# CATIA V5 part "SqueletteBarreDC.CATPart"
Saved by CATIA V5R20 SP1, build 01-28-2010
Part number: SqueletteBarreDC
Publications: "Point.1", "Point.2", "Droite.1", "Droite.2", "Droite.3", "Point.3", "Droite.4", "LongueurDC"
Bounding box of the stored display mesh (mm): x -20 to 20, y -100 to 100, z 0 to 0
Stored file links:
  C:\Documents and Settings\ndumont\Bureau\ndumont_CAO\SqueletteBarreDC.CATPart
  C:\Documents and Settings\ndumont\Bureau\ndumont_CAO\Squelette.CATProduct
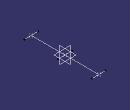
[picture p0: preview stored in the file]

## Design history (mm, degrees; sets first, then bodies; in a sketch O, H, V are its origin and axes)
Parameters
  LongueurDC = 200 mm {= 2*External.LongueurAB}
External parameters (linked from other documents)
  External.LongueurAB = 100 mm
Set1
  Point1: (0, 100 {= LongueurDC /2}, 0)
  Point2: (0, -100 {= -LongueurDC /2}, 0)
  Line1: type PtPt, FirstPoint Point2, SecondPoint Point1
  Line2: type PtDir, RefPoint Point2, Direction yz-plane, Start -20, End 20
  Line3: type PtDir, RefPoint Point1, Direction yz-plane, Start -20, End 20
  Point3: (0, 0, 0)
  Line4: type PtDir, RefPoint Point3, Direction yz-plane, Start -20, End 20
Body1 (main body)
